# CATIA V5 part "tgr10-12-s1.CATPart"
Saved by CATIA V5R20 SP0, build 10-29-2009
Part number: TGR10-12-S1
Revision: 3
Definition: design
Nomenclature: TGR10-12-S1
Source: made
Description: NOT SPECIFIED
Bounding box of the stored display mesh (mm): x -22 to 0.8, y 0 to 10, z -5 to 5
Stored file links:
  C:\Users\Raffaele\Desktop\3D X SITO CF\I-MOLD\TGR-S1\tgr10-s1.step\tgr10-12-s1.CATPart
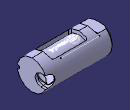
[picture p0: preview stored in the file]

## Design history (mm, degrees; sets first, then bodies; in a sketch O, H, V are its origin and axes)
Set1
  Line1 "LINE #4421": stored without definition
  DatumCurve1 "COMPOSITE_CURVE #4481"
  DatumCurve2 "COMPOSITE_CURVE #4532"
  DatumCurve3 "COMPOSITE_CURVE #4676"
  DatumCurve4 "COMPOSITE_CURVE #4755"
  DatumCurve5 "COMPOSITE_CURVE #4784"
  DatumCurve6 "COMPOSITE_CURVE #4842"
  DatumCurve7 "COMPOSITE_CURVE #4899"
  DatumCurve8 "COMPOSITE_CURVE #4942"
  DatumCurve9 "COMPOSITE_CURVE #5171"
  DatumCurve10 "COMPOSITE_CURVE #5198"
  DatumSurface1 "OPEN_SHELL #4411"
Body1 "MANIFOLD_SOLID_BREP #4412" (main body)
  Solid1: solid without history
